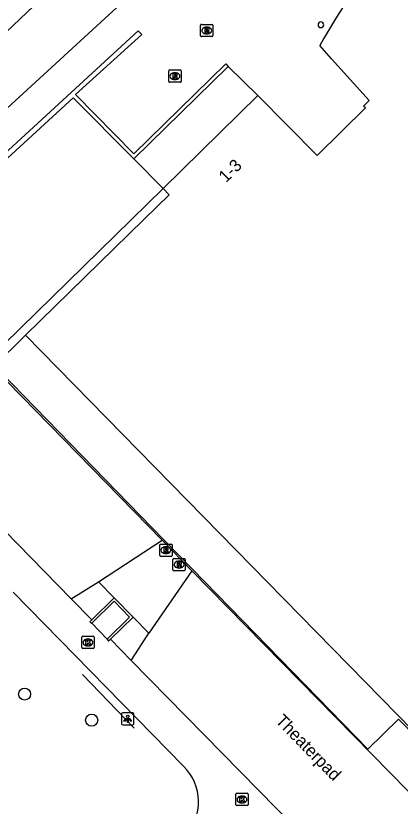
# Model space of a CAD drawing. Extents: x 161402 to 161933, y 381650 to 382313.
# Drawn here: x 161720.7 to 161751.9, y 382152.2 to 382216.4 of the extents above; entities that cross this region are included whole.
import ezdxf

# ---------------------------------------------------------------- set-up
doc = ezdxf.new("R2010")
doc.units = 0
for name, color, linetype in [('IMGEO_Boom', 7, 'Continuous'), ('IMGEO_Hek', 7, 'Continuous'), ('IMGEO_Kolk', 7, 'Continuous'), ('IMGEO_Lichtpunt', 7, 'Continuous'), ('IMGEO_Muur', 7, 'Continuous'), ('IMGEO_Openbare_ruimte_label', 7, 'Continuous'), ('IMGEO_Pand', 7, 'Continuous'), ('IMGEO_Pand_nummerreeks', 7, 'Continuous'), ('IMGEO_Pand_overbouw', 7, 'Continuous'), ('IMGEO_Rijbaan_lokaal_open', 7, 'Continuous'), ('IMGEO_Rioolput', 7, 'Continuous'), ('IMGEO_Voetpad_gesloten', 7, 'Continuous'), ('IMGEO_Voetpad_op_trap', 7, 'Continuous'), ('IMGEO_Voetpad_open', 7, 'Continuous')]:
    doc.layers.add(name, color=color, linetype=linetype)

msp = doc.modelspace()

# ---------------------------------------------------------------- linework, layer by layer
at = {"layer": 'IMGEO_Boom'}
for centre in [(161721.378, 382161.296), (161726.827, 382159.18)]:
    msp.add_circle(centre, 0.489, dxfattribs=at)
at = {"layer": 'IMGEO_Hek'}
msp.add_lwpolyline([(161726.851, 382167.068), (161728.078, 382165.762)], dxfattribs=at)
at = {"layer": 'IMGEO_Kolk'}
for p, q in [((161726.025, 382165.074), (161726.025, 382165.926)), ((161726.1, 382166), (161726.952, 382166)), ((161726.513, 382165.78), (161726.538, 382165.78)), ((161727.026, 382165.926), (161727.026, 382165.074)), ((161726.952, 382165), (161726.1, 382165)), ((161726.536, 382165.22), (161726.511, 382165.22)), ((161738.535, 382152.306), (161738.535, 382153.158)), ((161738.61, 382153.232), (161739.462, 382153.232)), ((161739.023, 382153.012), (161739.048, 382153.012)), ((161739.536, 382153.158), (161739.536, 382152.306)), ((161739.462, 382152.232), (161738.61, 382152.232)), ((161739.046, 382152.452), (161739.021, 382152.452))]:
    msp.add_line(p, q, dxfattribs=at)
for points in [[(161726.025, 382165.074), (161726.025, 382165.926)], [(161726.1, 382166), (161726.952, 382166)], [(161726.346, 382165.7), (161726.469, 382165.7), (161726.469, 382165.549), (161726.599, 382165.7), (161726.763, 382165.7), (161726.617, 382165.549), (161726.77, 382165.3), (161726.618, 382165.3), (161726.533, 382165.464), (161726.469, 382165.397), (161726.469, 382165.3), (161726.346, 382165.3), (161726.346, 382165.7)], [(161727.026, 382165.926), (161727.026, 382165.074)], [(161726.952, 382165), (161726.1, 382165)], [(161738.535, 382152.306), (161738.535, 382153.158)], [(161738.61, 382153.232), (161739.462, 382153.232)], [(161738.856, 382152.932), (161738.979, 382152.932), (161738.979, 382152.781), (161739.109, 382152.932), (161739.273, 382152.932), (161739.127, 382152.781), (161739.28, 382152.532), (161739.128, 382152.532), (161739.043, 382152.696), (161738.979, 382152.629), (161738.979, 382152.532), (161738.856, 382152.532), (161738.856, 382152.932)], [(161739.536, 382153.158), (161739.536, 382152.306)], [(161739.462, 382152.232), (161738.61, 382152.232)]]:
    msp.add_lwpolyline(points, dxfattribs=at)
for centre, start, end in [((161726.102, 382165.924), 91.55205, 178.44795), ((161726.102, 382165.924), 91.55205, 178.44795), ((161726.95, 382165.924), 1.55205, 88.44795), ((161726.95, 382165.924), 1.55205, 88.44795), ((161726.102, 382165.076), 181.55205, 268.44795), ((161726.102, 382165.076), 181.55205, 268.44795), ((161726.95, 382165.076), 271.55205, 358.44795), ((161726.95, 382165.076), 271.55205, 358.44795), ((161738.612, 382153.156), 91.55205, 178.44795), ((161738.612, 382153.156), 91.55205, 178.44795), ((161739.46, 382153.156), 1.55205, 88.44795), ((161739.46, 382153.156), 1.55205, 88.44795), ((161738.612, 382152.308), 181.55205, 268.44795), ((161738.612, 382152.308), 181.55205, 268.44795), ((161739.46, 382152.308), 271.55205, 358.44795), ((161739.46, 382152.308), 271.55205, 358.44795)]:
    msp.add_arc(centre, 0.0765, start, end, dxfattribs=at)
for centre, major_axis, ratio, start_param, end_param in [((161726.512, 382165.5), (-0.387, 0.002), 0.722429, 4.712389, 7.853982), ((161726.537, 382165.5), (-0.39, 0.002), 0.717154, 1.570796, 4.712389), ((161739.022, 382152.732), (-0.387, 0.002), 0.722429, 4.712389, 7.853982), ((161739.047, 382152.732), (-0.39, 0.002), 0.717154, 1.570796, 4.712389)]:
    msp.add_ellipse(centre, major_axis=major_axis, ratio=ratio, start_param=start_param, end_param=end_param, dxfattribs=at)
at = {"layer": 'IMGEO_Lichtpunt'}
for p, q in [((161730.164, 382159.785), (161729.356, 382159.785)), ((161730.164, 382159.785), (161729.356, 382159.785)), ((161729.262, 382159.69), (161729.262, 382158.883)), ((161729.262, 382159.69), (161729.262, 382158.883)), ((161730.258, 382158.883), (161730.258, 382159.69)), ((161730.258, 382158.883), (161730.258, 382159.69)), ((161729.356, 382158.789), (161730.164, 382158.789)), ((161729.356, 382158.789), (161730.164, 382158.789))]:
    msp.add_line(p, q, dxfattribs=at)
for points in [[(161729.636, 382159.354), (161729.675, 382159.326), (161729.487, 382159.064), (161729.449, 382159.091), (161729.636, 382159.354)], [(161729.738, 382159.306), (161729.785, 382159.306), (161729.785, 382158.984), (161729.738, 382158.984), (161729.738, 382159.306)], [(161729.848, 382159.326), (161729.886, 382159.353), (161730.073, 382159.091), (161730.034, 382159.063), (161729.848, 382159.326)]]:
    msp.add_lwpolyline(points, dxfattribs=at)
msp.add_circle((161729.761, 382159.488), 0.0994, dxfattribs=at)
for centre, start, end in [((161729.356, 382159.69), 90, 180), ((161729.356, 382159.69), 90, 180), ((161730.164, 382159.69), 0, 90), ((161730.164, 382159.69), 0, 90), ((161729.356, 382158.883), 180, 270), ((161729.356, 382158.883), 180, 270), ((161730.164, 382158.883), 270, 0), ((161730.164, 382158.883), 270, 360)]:
    msp.add_arc(centre, 0.0946, start, end, dxfattribs=at)
at = {"layer": 'IMGEO_Muur'}
for points in [[(161704.004, 382190.216), (161703.837, 382190.381), (161703.725, 382190.486), (161730.601, 382215.217), (161730.896, 382214.926), (161725.521, 382210.052), (161730.265, 382205.223), (161737.712, 382212.535), (161737.927, 382212.338)], [(161737.927, 382212.338), (161730.255, 382204.824)], [(161730.255, 382204.824), (161725.317, 382209.785), (161714.96, 382200.272)], [(161728.661, 382169.134), (161726.833, 382167.332)], [(161726.851, 382167.068), (161728.644, 382168.842), (161729.907, 382167.555), (161728.078, 382165.762)], [(161730.192, 382167.561), (161728.661, 382169.134)], [(161730.192, 382167.561), (161728.36, 382165.756)], [(161726.833, 382167.332), (161726.677, 382167.178), (161726.851, 382167.068)], [(161728.078, 382165.762), (161728.206, 382165.605), (161728.36, 382165.756)], [(161726.092, 382162.883), (161730.28, 382158.537)]]:
    msp.add_lwpolyline(points, dxfattribs=at)
at = {"layer": 'IMGEO_Pand'}
for points in [[(161740.314, 382209.981), (161745.139, 382205.091), (161749.061, 382208.961), (161748.921, 382209.103), (161749.374, 382209.55), (161746.316, 382212.958), (161745.352, 382214.033)], [(161732.627, 382202.397), (161740.314, 382209.981)], [(161732.627, 382202.397), (161733.12, 382201.899), (161731.074, 382199.9), (161721.45, 382190.492)], [(161762.198, 382148.594), (161761.744, 382149.047), (161761.891, 382149.186), (161762.139, 382149.42), (161762.295, 382149.283), (161763.101, 382150.057), (161760.483, 382152.716), (161759.531, 382151.588), (161721.45, 382190.492)]]:
    msp.add_lwpolyline(points, dxfattribs=at)
for centre, radius, start, end in [((161816.968, 382172.845), 82.616, 143.12172, 150.09585), ((161745.445, 382215.72), 0.23, 90, 270), ((161745.445, 382215.72), 0.23, 270, 90)]:
    msp.add_arc(centre, radius, start, end, dxfattribs=at)
at = {"layer": 'IMGEO_Pand_overbouw'}
msp.add_lwpolyline([(161761.891, 382149.186), (161762.139, 382149.42), (161762.295, 382149.283), (161763.101, 382150.057), (161760.483, 382152.716), (161759.531, 382151.588), (161721.45, 382190.492), (161731.074, 382199.9), (161733.12, 382201.899), (161732.627, 382202.397), (161718.426, 382188.506), (161732.696, 382173.838), (161734.999, 382171.47), (161749.249, 382156.824), (161751.751, 382159.273), (161759.445, 382151.424), (161759.582, 382151.549)], close=True, dxfattribs=at)
at = {"layer": 'IMGEO_Rijbaan_lokaal_open'}
for points in [[(161755.602, 382242.666), (161739.772, 382227.133), (161733.859, 382221.725), (161710.972, 382200.713)], [(161748.845, 382243.038), (161728.253, 382223.117), (161713.169, 382208.748), (161711.914, 382207.765)]]:
    msp.add_lwpolyline(points, dxfattribs=at)
at = {"layer": 'IMGEO_Rioolput'}
for p, q in [((161735.676, 382214.83), (161735.676, 382215.682)), ((161735.751, 382215.756), (161736.603, 382215.756)), ((161736.677, 382215.682), (161736.677, 382214.83)), ((161736.187, 382214.976), (161736.162, 382214.976)), ((161736.164, 382215.536), (161736.189, 382215.536)), ((161736.603, 382214.756), (161735.751, 382214.756)), ((161733.088, 382211.119), (161733.088, 382211.971)), ((161733.163, 382212.045), (161734.015, 382212.045)), ((161733.576, 382211.825), (161733.601, 382211.825)), ((161734.089, 382211.971), (161734.089, 382211.119)), ((161733.599, 382211.265), (161733.574, 382211.265)), ((161734.015, 382211.045), (161733.163, 382211.045)), ((161732.355, 382172.571), (161732.355, 382173.423)), ((161732.43, 382173.497), (161733.282, 382173.497)), ((161732.843, 382173.277), (161732.868, 382173.277)), ((161733.356, 382173.423), (161733.356, 382172.571)), ((161732.866, 382172.717), (161732.841, 382172.717)), ((161733.282, 382172.497), (161732.43, 382172.497)), ((161733.429, 382171.402), (161733.429, 382172.254)), ((161733.504, 382172.328), (161734.356, 382172.328)), ((161733.917, 382172.108), (161733.942, 382172.108)), ((161734.43, 382172.254), (161734.43, 382171.402)), ((161734.356, 382171.328), (161733.504, 382171.328)), ((161733.94, 382171.548), (161733.915, 382171.548))]:
    msp.add_line(p, q, dxfattribs=at)
for points in [[(161735.676, 382214.83), (161735.676, 382215.682)], [(161735.751, 382215.756), (161736.603, 382215.756)], [(161736.677, 382215.682), (161736.677, 382214.83)], [(161736.265, 382215.454), (161736.013, 382215.456), (161736.013, 382215.056)], [(161736.013, 382215.056), (161736.137, 382215.056), (161736.137, 382215.218), (161736.148, 382215.218)], [(161736.191, 382215.375), (161736.137, 382215.375), (161736.137, 382215.294)], [(161736.137, 382215.294), (161736.189, 382215.294)], [(161736.195, 382215.189), (161736.266, 382215.056), (161736.406, 382215.056), (161736.341, 382215.182)], [(161736.603, 382214.756), (161735.751, 382214.756)], [(161733.088, 382211.119), (161733.088, 382211.971)], [(161733.163, 382212.045), (161734.015, 382212.045)], [(161734.089, 382211.971), (161734.089, 382211.119)], [(161733.677, 382211.743), (161733.425, 382211.745), (161733.425, 382211.345)], [(161733.425, 382211.345), (161733.549, 382211.345), (161733.549, 382211.507), (161733.56, 382211.507)], [(161733.603, 382211.664), (161733.549, 382211.664), (161733.549, 382211.583)], [(161733.549, 382211.583), (161733.601, 382211.583)], [(161733.607, 382211.478), (161733.678, 382211.345), (161733.818, 382211.345), (161733.753, 382211.471)], [(161734.015, 382211.045), (161733.163, 382211.045)], [(161732.355, 382172.571), (161732.355, 382173.423)], [(161732.43, 382173.497), (161733.282, 382173.497)], [(161732.944, 382173.195), (161732.692, 382173.197), (161732.692, 382172.797)], [(161733.356, 382173.423), (161733.356, 382172.571)], [(161732.692, 382172.797), (161732.816, 382172.797), (161732.816, 382172.959), (161732.827, 382172.959)], [(161732.87, 382173.116), (161732.816, 382173.116), (161732.816, 382173.035)], [(161732.816, 382173.035), (161732.868, 382173.035)], [(161732.874, 382172.93), (161732.945, 382172.797), (161733.085, 382172.797), (161733.02, 382172.923)], [(161733.282, 382172.497), (161732.43, 382172.497)], [(161733.429, 382171.402), (161733.429, 382172.254)], [(161733.504, 382172.328), (161734.356, 382172.328)], [(161734.018, 382172.026), (161733.766, 382172.028), (161733.766, 382171.628)], [(161733.944, 382171.947), (161733.89, 382171.947), (161733.89, 382171.866)], [(161734.43, 382172.254), (161734.43, 382171.402)], [(161734.356, 382171.328), (161733.504, 382171.328)], [(161733.766, 382171.628), (161733.89, 382171.628), (161733.89, 382171.79), (161733.901, 382171.79)], [(161733.89, 382171.866), (161733.942, 382171.866)], [(161733.948, 382171.761), (161734.019, 382171.628), (161734.159, 382171.628), (161734.094, 382171.754)]]:
    msp.add_lwpolyline(points, dxfattribs=at)
for centre, radius, start, end in [((161735.753, 382215.68), 0.0765, 91.55205, 178.44795), ((161735.753, 382215.68), 0.0765, 91.55205, 178.44795), ((161736.601, 382215.68), 0.0765, 1.55205, 88.44795), ((161736.601, 382215.68), 0.0765, 1.55205, 88.44795), ((161736.147, 382215.165), 0.0533, 26.02933, 88.69889), ((161736.173, 382215.483), 0.19, 274.7715, 282.96867), ((161736.197, 382215.279), 0.0964, 77.00612, 93.18647), ((161736.211, 382215.336), 0.0378, 276.66336, 79.67722), ((161736.264, 382215.344), 0.109, 350.36119, 89.41601), ((161736.262, 382215.344), 0.112, 277.58423, 350.98172), ((161736.246, 382215.129), 0.108, 29.51342, 73.79051), ((161735.753, 382214.832), 0.0765, 181.55205, 268.44795), ((161735.753, 382214.832), 0.0765, 181.55205, 268.44795), ((161736.601, 382214.832), 0.0765, 271.55205, 358.44795), ((161736.601, 382214.832), 0.0765, 271.55205, 358.44795), ((161733.165, 382211.969), 0.0765, 91.55205, 178.44795), ((161733.165, 382211.969), 0.0765, 91.55205, 178.44795), ((161734.013, 382211.969), 0.0765, 1.55205, 88.44795), ((161734.013, 382211.969), 0.0765, 1.55205, 88.44795), ((161733.165, 382211.121), 0.0765, 181.55205, 268.44795), ((161733.165, 382211.121), 0.0765, 181.55205, 268.44795), ((161733.559, 382211.454), 0.0533, 26.02933, 88.69889), ((161733.585, 382211.772), 0.19, 274.7715, 282.96867), ((161733.609, 382211.568), 0.0964, 77.00612, 93.18647), ((161733.623, 382211.625), 0.0378, 276.66336, 79.67722), ((161733.676, 382211.633), 0.109, 350.36119, 89.41601), ((161733.674, 382211.633), 0.112, 277.58423, 350.98172), ((161733.658, 382211.418), 0.108, 29.51342, 73.79051), ((161734.013, 382211.121), 0.0765, 271.55205, 358.44795), ((161734.013, 382211.121), 0.0765, 271.55205, 358.44795), ((161732.432, 382173.421), 0.0765, 91.55205, 178.44795), ((161732.432, 382173.421), 0.0765, 91.55205, 178.44795), ((161732.943, 382173.085), 0.109, 350.36119, 89.41601), ((161733.28, 382173.421), 0.0765, 1.55205, 88.44795), ((161733.28, 382173.421), 0.0765, 1.55205, 88.44795), ((161732.432, 382172.573), 0.0765, 181.55205, 268.44795), ((161732.432, 382172.573), 0.0765, 181.55205, 268.44795), ((161732.826, 382172.906), 0.0533, 26.02933, 88.69889), ((161732.852, 382173.224), 0.19, 274.7715, 282.96867), ((161732.876, 382173.02), 0.0964, 77.00612, 93.18647), ((161732.89, 382173.077), 0.0378, 276.66336, 79.67722), ((161732.941, 382173.085), 0.112, 277.58423, 350.98172), ((161732.925, 382172.87), 0.108, 29.51342, 73.79051), ((161733.28, 382172.573), 0.0765, 271.55205, 358.44795), ((161733.28, 382172.573), 0.0765, 271.55205, 358.44795), ((161733.506, 382172.252), 0.0765, 91.55205, 178.44795), ((161733.506, 382172.252), 0.0765, 91.55205, 178.44795), ((161733.95, 382171.851), 0.0964, 77.00612, 93.18647), ((161733.964, 382171.908), 0.0378, 276.66336, 79.67722), ((161734.017, 382171.916), 0.109, 350.36119, 89.41601), ((161734.354, 382172.252), 0.0765, 1.55205, 88.44795), ((161734.354, 382172.252), 0.0765, 1.55205, 88.44795), ((161733.506, 382171.404), 0.0765, 181.55205, 268.44795), ((161733.506, 382171.404), 0.0765, 181.55205, 268.44795), ((161733.9, 382171.737), 0.0533, 26.02933, 88.69889), ((161733.926, 382172.055), 0.19, 274.7715, 282.96867), ((161734.015, 382171.916), 0.112, 277.58423, 350.98172), ((161733.999, 382171.701), 0.108, 29.51342, 73.79051), ((161734.354, 382171.404), 0.0765, 271.55205, 358.44795), ((161734.354, 382171.404), 0.0765, 271.55205, 358.44795)]:
    msp.add_arc(centre, radius, start, end, dxfattribs=at)
for centre, major_axis, ratio, start_param, end_param in [((161736.163, 382215.256), (-0.387, 0.002), 0.722429, 4.712389, 7.853982), ((161736.188, 382215.256), (-0.39, 0.002), 0.717154, 1.570796, 4.712389), ((161733.575, 382211.545), (-0.387, 0.002), 0.722429, 4.712389, 7.853982), ((161733.6, 382211.545), (-0.39, 0.002), 0.717154, 1.570796, 4.712389), ((161732.842, 382172.997), (-0.387, 0.002), 0.722429, 4.712389, 7.853982), ((161732.867, 382172.997), (-0.39, 0.002), 0.717154, 1.570796, 4.712389), ((161733.916, 382171.828), (-0.387, 0.002), 0.722429, 4.712389, 7.853982), ((161733.941, 382171.828), (-0.39, 0.002), 0.717154, 1.570796, 4.712389)]:
    msp.add_ellipse(centre, major_axis=major_axis, ratio=ratio, start_param=start_param, end_param=end_param, dxfattribs=at)
at = {"layer": 'IMGEO_Voetpad_gesloten'}
for points in [[(161727.393, 382170.437), (161732.558, 382173.814)], [(161732.558, 382173.814), (161734.96, 382171.316)], [(161734.96, 382171.316), (161731.457, 382166.262)], [(161727.393, 382170.437), (161728.661, 382169.134)], [(161731.457, 382166.262), (161730.192, 382167.561)], [(161728.078, 382165.762), (161726.851, 382167.068)]]:
    msp.add_lwpolyline(points, dxfattribs=at)
at = {"layer": 'IMGEO_Voetpad_op_trap'}
for points in [[(161725.159, 382169.045), (161727.393, 382170.437)], [(161730.041, 382164.042), (161731.457, 382166.262)]]:
    msp.add_lwpolyline(points, dxfattribs=at)
at = {"layer": 'IMGEO_Voetpad_open'}
for points in [[(161740.314, 382209.981), (161737.927, 382212.338)], [(161730.255, 382204.824), (161732.627, 382202.397)], [(161721.45, 382190.492), (161718.791, 382187.892)], [(161718.791, 382187.892), (161732.558, 382173.814)], [(161712.113, 382182.395), (161725.159, 382169.045)], [(161734.96, 382171.316), (161756.887, 382148.953)], [(161734.284, 382155.436), (161720.442, 382169.591)], [(161726.833, 382167.332), (161725.159, 382169.045)], [(161728.36, 382165.756), (161730.041, 382164.042)], [(161730.041, 382164.042), (161750.723, 382142.947)]]:
    msp.add_lwpolyline(points, dxfattribs=at)
msp.add_arc((161731.487, 382152.532), 4.032, 316.50341, 46.07895, dxfattribs=at)

# ---------------------------------------------------------------- texts
at = {"layer": 'IMGEO_Openbare_ruimte_label'}
msp.add_text('Theaterpad', height=1, rotation=314.27067, dxfattribs=at).set_placement((161741.695, 382159.064))
at = {"layer": 'IMGEO_Pand_nummerreeks'}
msp.add_text('1-3', height=1, rotation=44.61596, dxfattribs=at).set_placement((161737.735, 382202.829))

doc.saveas('drawing.dxf')
